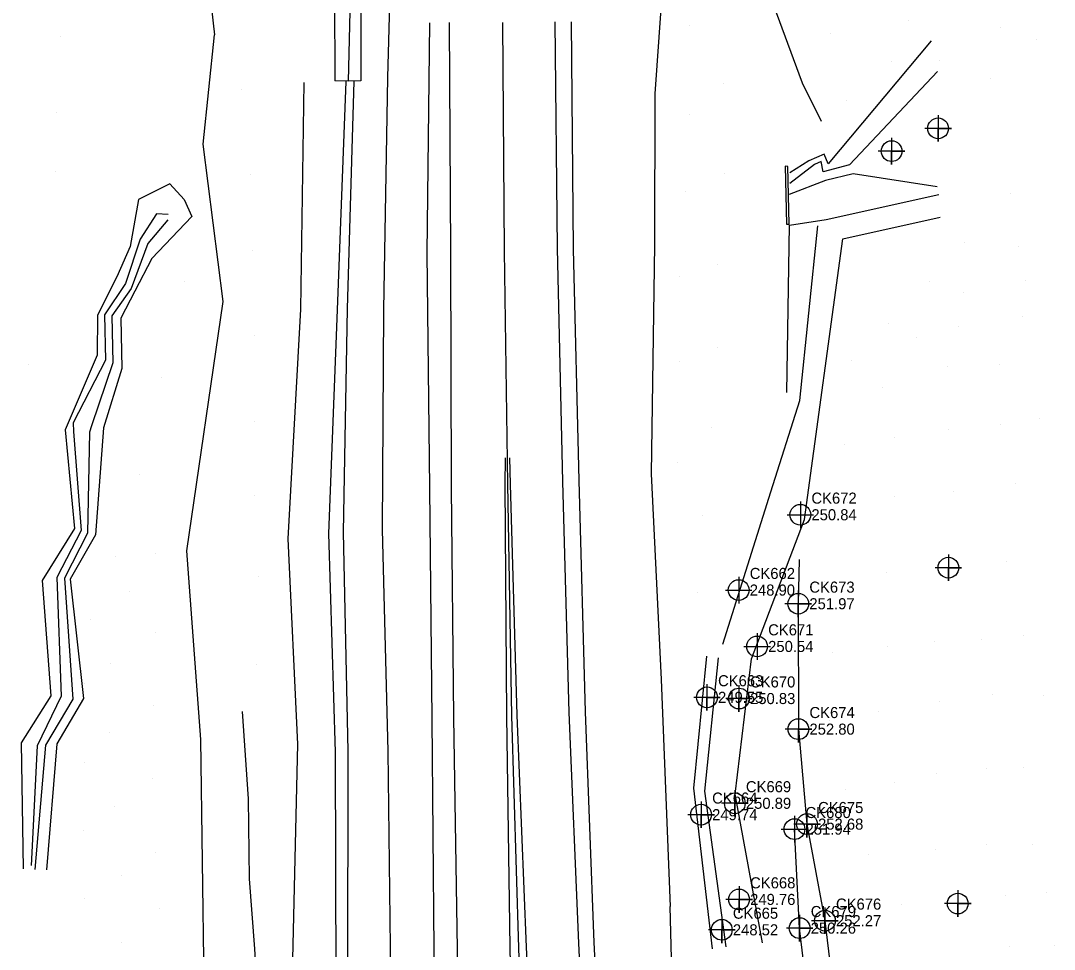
# Model space of a CAD drawing. Extents: x 1941547 to 1942851, y 663002 to 668358.
# Drawn here: x 1941855.2 to 1942088.7, y 667204.6 to 667414.3 of the extents above; entities that cross this region are included whole.
import ezdxf

# ---------------------------------------------------------------- set-up
doc = ezdxf.new("R2010")
doc.units = 0
for name, color, linetype in [('CTL NGS Vertical CELL', 7, 'Continuous'), ('Default Symbol CELL', 7, 'Continuous'), ('Exist DTM Breakline Cogo Elevation', 7, 'Continuous'), ('Exist DTM Breakline Cogo Number', 7, 'Continuous'), ('Exist DTM Breakline Cogo Point CELL', 7, 'Continuous'), ('Exist DTM Drainline Cogo Elevation', 7, 'Continuous'), ('Exist Property Iron Pin Cogo Number', 7, 'Continuous'), ('Exist Roads EOP Cogo Elevation', 7, 'Continuous'), ('Exist Roads EOP Cogo Number', 7, 'Continuous'), ('Exist Roads EOT', 7, 'Continuous'), ('Exist Utilities Telephone UG Cable SUE LOS C Cogo Elevation', 7, 'Continuous'), ('Exist Utilities Telephone UG FO SUE LOS C Cogo Elevation', 7, 'Continuous'), ('PH Exist DTM Breakline', 7, 'Continuous'), ('PH Exist DTM Point', 7, 'Continuous')]:
    doc.layers.add(name, color=color, linetype=linetype)

msp = doc.modelspace()

# ---------------------------------------------------------------- linework, layer by layer
at = {"layer": 'CTL NGS Vertical CELL'}
for points in [[(1942062.3, 667402.82), (1942042.4, 667381.75), (1942036.45, 667380.14), (1942035.97, 667382.48), (1942034.45, 667381.81), (1942028.95, 667377.47)], [(1941944.36, 666841.1), (1941940.55, 666899.2), (1941939.33, 666951.2), (1941935.62, 666998.45), (1941934.74, 667049.89), (1941931.25, 667098.44), (1941929.85, 667149.11), (1941926.42, 667197.25), (1941926.31, 667249.1), (1941924.77, 667298.53), (1941926.78, 667349), (1941928.74, 667400.53)], [(1941946.98, 666841.87), (1941943.17, 666899.66), (1941941.62, 666951.26), (1941938.82, 666998.62), (1941936.61, 667049.98), (1941933.24, 667098.55), (1941932.35, 667149.21), (1941929.12, 667196.95), (1941929.17, 667249.39), (1941928.09, 667298.81), (1941929.02, 667349.18), (1941930.48, 667400.62)], [(1942062.17, 667376.74), (1942043.22, 667379.65), (1942036.98, 667378.19), (1942028.76, 667375)], [(1941888.49, 667370.51), (1941885.84, 667370.67), (1941882.18, 667364.91), (1941878.86, 667354.96), (1941874.13, 667347.86), (1941874.39, 667337.64), (1941867.06, 667323.46), (1941867.16, 667321.53), (1941868.86, 667299.18), (1941863.38, 667288.53), (1941864.32, 667261.75), (1941858.91, 667250.6), (1941857.58, 667223.58)], [(1941888.41, 667369.27), (1941883.95, 667363.99), (1941880.16, 667353.83), (1941875.77, 667347.61), (1941876.03, 667337), (1941871.17, 667322.82), (1941870.74, 667321.4), (1941870.26, 667298.59), (1941865.12, 667288.42), (1941866.95, 667261.11), (1941860.83, 667250.71), (1941858.37, 667222.65)], [(1942011.46, 667204.71), (1942007.26, 667240.97), (1942010.15, 667270.83)], [(1942014.53, 667205.16), (1942009.75, 667240.36), (1942012.79, 667270.45)]]:
    msp.add_lwpolyline(points, dxfattribs=at)
at = {"layer": 'Exist DTM Breakline Cogo Number'}
for points in [[(1942031.29, 667305.73), (1942031.29, 667302.73)], [(1942028.29, 667302.73), (1942031.29, 667302.73)], [(1942031.29, 667302.73), (1942034.29, 667302.73)], [(1942031.29, 667302.73), (1942031.29, 667299.73)], [(1942017.36, 667288.73), (1942017.36, 667285.73)], [(1942014.36, 667285.73), (1942017.36, 667285.73)], [(1942017.36, 667285.73), (1942020.36, 667285.73)], [(1942017.36, 667285.73), (1942017.36, 667282.73)], [(1942021.52, 667276), (1942021.52, 667273)], [(1942018.52, 667273), (1942021.52, 667273)], [(1942021.52, 667273), (1942024.52, 667273)], [(1942021.52, 667273), (1942021.52, 667270)], [(1942029.96, 667234.76), (1942029.96, 667231.76)], [(1942026.96, 667231.76), (1942029.96, 667231.76)], [(1942029.96, 667231.76), (1942032.96, 667231.76)], [(1942029.96, 667231.76), (1942029.96, 667228.76)]]:
    msp.add_lwpolyline(points, dxfattribs=at)
for centre in [(1942031.29, 667302.73), (1942017.36, 667285.73), (1942021.52, 667273), (1942029.96, 667231.76)]:
    msp.add_circle(centre, 2.34, dxfattribs=at)
at = {"layer": 'Exist DTM Drainline Cogo Elevation'}
for points in [[(1942062.4, 667392.95), (1942062.4, 667386.95), (1942062.4, 667389.95), (1942065.4, 667389.95), (1942059.4, 667389.95)], [(1942051.9, 667387.81), (1942051.9, 667381.81), (1942051.9, 667384.81), (1942054.9, 667384.81), (1942048.9, 667384.81)], [(1942064.72, 667293.78), (1942064.72, 667287.78), (1942064.72, 667290.78), (1942067.72, 667290.78), (1942061.72, 667290.78)], [(1942066.84, 667217.95), (1942066.84, 667211.95), (1942066.84, 667214.95), (1942069.84, 667214.95), (1942063.84, 667214.95)]]:
    msp.add_lwpolyline(points, dxfattribs=at)
for centre in [(1942062.4, 667389.95), (1942051.9, 667384.81), (1942064.72, 667290.78), (1942066.84, 667214.95)]:
    msp.add_circle(centre, 2.34, dxfattribs=at)
at = {"layer": 'Exist Property Iron Pin Cogo Number'}
msp.add_lwpolyline([(1942008.85, 666690.79), (1942002.07, 666741.6), (1941996.47, 666793.56), (1941990.89, 666844.38), (1941986.33, 666894.98), (1941981.96, 666947.23), (1941978.03, 666998.38), (1941974.77, 667049.54), (1941971.64, 667101.97), (1941969.4, 667152.95), (1941967.69, 667204.95), (1941966.16, 667257.35), (1941965.22, 667309.63), (1941964.5, 667362.27), (1941964.07, 667413.88)], dxfattribs=at)
at = {"layer": 'Exist Roads EOP Cogo Number'}
for points in [[(1942030.82, 667285.64), (1942030.82, 667279.64), (1942030.82, 667282.64), (1942033.82, 667282.64), (1942027.82, 667282.64)], [(1942010.2, 667264.51), (1942010.2, 667258.51), (1942010.2, 667261.51), (1942013.2, 667261.51), (1942007.2, 667261.51)], [(1942017.43, 667264.24), (1942017.43, 667258.24), (1942017.43, 667261.24), (1942020.43, 667261.24), (1942014.43, 667261.24)], [(1942030.85, 667257.33), (1942030.85, 667251.33), (1942030.85, 667254.33), (1942033.85, 667254.33), (1942027.85, 667254.33)], [(1942016.49, 667240.59), (1942016.49, 667234.59), (1942016.49, 667237.59), (1942019.49, 667237.59), (1942013.49, 667237.59)], [(1942008.87, 667238.02), (1942008.87, 667232.02), (1942008.87, 667235.02), (1942011.87, 667235.02), (1942005.87, 667235.02)], [(1942032.79, 667235.89), (1942032.79, 667229.89), (1942032.79, 667232.89), (1942035.79, 667232.89), (1942029.79, 667232.89)], [(1942017.45, 667218.89), (1942017.45, 667212.89), (1942017.45, 667215.89), (1942020.45, 667215.89), (1942014.45, 667215.89)], [(1942036.84, 667214.09), (1942036.84, 667208.09), (1942036.84, 667211.09), (1942039.84, 667211.09), (1942033.84, 667211.09)], [(1942013.55, 667212.03), (1942013.55, 667206.03), (1942013.55, 667209.03), (1942016.55, 667209.03), (1942010.55, 667209.03)], [(1942031.13, 667212.41), (1942031.13, 667206.41), (1942031.13, 667209.41), (1942034.13, 667209.41), (1942028.13, 667209.41)]]:
    msp.add_lwpolyline(points, dxfattribs=at)
for centre in [(1942030.82, 667282.64), (1942010.2, 667261.51), (1942017.43, 667261.24), (1942030.85, 667254.33), (1942016.49, 667237.59), (1942008.87, 667235.02), (1942032.79, 667232.89), (1942017.45, 667215.89), (1942036.84, 667211.09), (1942013.55, 667209.03), (1942031.13, 667209.41)]:
    msp.add_circle(centre, 2.34, dxfattribs=at)
at = {"layer": 'Exist Roads EOT'}
for points in [[(1941951.98, 667413.81), (1941952.26, 667362.04), (1941952.46, 667308.89), (1941952.97, 667256.94), (1941953.75, 667204.68), (1941954.75, 667152.02), (1941956.26, 667100.95), (1941958.71, 667048.32), (1941960.84, 666996.9), (1941962.55, 666945.54), (1941964.6, 666892.87), (1941965.91, 666841.69), (1941967.14, 666790.13), (1941967.35, 666775.96), (1941965.99, 666756.26), (1941960.31, 666738.22), (1941950.2, 666725.25), (1941933.38, 666712.58), (1941911.61, 666702.83), (1941884.69, 666696.42), (1941884.07, 666696.32)], [(1942026.6, 666693.52), (1942019.88, 666743.94), (1942013.54, 666795.86), (1942007.82, 666846.76), (1942002.76, 666897.1), (1941997.85, 666949.23), (1941993.62, 666999.88), (1941989.95, 667051.06), (1941986.57, 667103.22), (1941983.76, 667154.19), (1941981.25, 667205.98), (1941979.11, 667258.1), (1941977.64, 667310.25), (1941976.44, 667362.8), (1941975.95, 667413.99)], [(1942003.35, 666690.27), (1941996.18, 666740.71), (1941990.55, 666792.95), (1941985.7, 666843.93), (1941981.39, 666894.52), (1941977.35, 666947.08), (1941973.82, 666998.13), (1941970.64, 667049.39), (1941968.27, 667101.82), (1941966.8, 667152.88), (1941965.74, 667205.04), (1941965, 667257.27), (1941964.59, 667309.55), (1941964.7, 667315.61)], [(1942014.4, 666691.83), (1942008.07, 666742.35), (1942001.91, 666794.2), (1941996.25, 666845.1), (1941991.05, 666895.6), (1941986.23, 666947.8), (1941981.87, 666998.75), (1941978.14, 667049.88), (1941974.78, 667102.32), (1941971.91, 667153.2), (1941969.44, 667205.09), (1941967.31, 667257.47), (1941965.84, 667309.66), (1941965.66, 667315.58)]]:
    msp.add_lwpolyline(points, dxfattribs=at)
at = {"layer": 'Exist Utilities Telephone UG Cable SUE LOS C Cogo Elevation'}
for points in [[(1941947.53, 667413.75), (1941946.96, 667361.74), (1941947.54, 667308.73), (1941948.08, 667256.56), (1941948.52, 667204.49), (1941949.24, 667151.67), (1941952.06, 667100.74), (1941955.32, 667048.01), (1941957.95, 666996.74), (1941959.85, 666945.25), (1941962.44, 666892.69), (1941963.58, 666841.54), (1941964.58, 666789.92), (1941964.71, 666776.07), (1941964.25, 666756.23), (1941958.52, 666739.42), (1941948.3, 666727.6), (1941930.93, 666716.38), (1941910.35, 666706.81), (1941883.98, 666699.72), (1941884.18, 666697.45), (1941835.96, 666689.1), (1941789.23, 666683.83)], [(1942029.9, 666693.84), (1942023.63, 666744.48), (1942017.17, 666796.27), (1942011.56, 666847.08), (1942006.59, 666897.47), (1942002, 666949.63), (1941997.54, 667000.16), (1941993.96, 667051.35), (1941990.36, 667103.49), (1941987.34, 667154.41), (1941984.74, 667206.16), (1941982.79, 667258.26), (1941981.31, 667310.45), (1941980.08, 667362.7), (1941979.57, 667414.02)], [(1942029.9, 666693.84), (1942023.63, 666744.48), (1942017.17, 666796.27), (1942011.56, 666847.08), (1942006.59, 666897.47), (1942002, 666949.63), (1941997.54, 667000.16), (1941993.96, 667051.35), (1941990.36, 667103.49), (1941987.34, 667154.41), (1941984.74, 667206.16), (1941982.79, 667258.26), (1941981.31, 667310.45), (1941980.08, 667362.7), (1941979.57, 667414.02)]]:
    msp.add_lwpolyline(points, dxfattribs=at)
at = {"layer": 'Exist Utilities Telephone UG FO SUE LOS C Cogo Elevation'}
for p, q in [((1941896.45, 667386.37), (1941898.94, 667411.09)), ((1941892.09, 667373.92), (1941888.92, 667377.45)), ((1941895.86, 667252), (1941892.74, 667294.6))]:
    msp.add_line(p, q, dxfattribs=at)
for points in [[(1941879.59, 667597.4), (1941880.92, 667567.08), (1941886.17, 667524.12), (1941892.76, 667465.98), (1941898.94, 667411.09)], [(1942058.97, 667471.88), (1942056.59, 667466.81), (1942043.21, 667443.37), (1942043.12, 667431.55), (1942034.51, 667434.31), (1942029.48, 667455.03), (1942025.79, 667468.06), (1942018.93, 667476.04), (1942008.95, 667476.26), (1941996.74, 667467.91), (1942001.16, 667436.21), (1941998.43, 667397.75), (1941998.37, 667363.65), (1941997.58, 667311.94), (1941999.85, 667265.5), (1942001.89, 667214.29)], [(1941953.68, 666843.33), (1941951.66, 666900.41), (1941949.77, 666951.26), (1941948.98, 666999.44), (1941946.86, 667050.67), (1941943.18, 667099.35), (1941941.85, 667149.88), (1941938.77, 667198.77), (1941938.16, 667249.33), (1941936.9, 667299.38), (1941937.19, 667349.01), (1941938.12, 667401.41), (1941938.73, 667423.66)], [(1942060.84, 667409.73), (1942037.57, 667381.92), (1942036.69, 667384.16), (1942033.22, 667382.61), (1942028.88, 667379.88)], [(1941940.44, 666840.55), (1941933.09, 666898.2), (1941933.3, 666950.95), (1941928.6, 666997.79), (1941925.81, 667049.37), (1941920.3, 667096.89), (1941919.5, 667148.93), (1941916.49, 667195.96), (1941917.83, 667250.95), (1941915.62, 667297.28), (1941918.48, 667349.12), (1941919.21, 667400.3)], [(1941892.74, 667294.6), (1941900.93, 667350.86), (1941896.45, 667386.37)], [(1942028.46, 667381.34), (1942027.89, 667381.4), (1942028.17, 667368.32), (1942028.73, 667368.31), (1942028.46, 667381.34)], [(1941888.92, 667377.45), (1941881.83, 667373.88), (1941879.94, 667363.26), (1941876.91, 667356.46), (1941872.54, 667347.76), (1941872.45, 667338.75), (1941865.25, 667321.87), (1941867.38, 667299.59), (1941860.05, 667287.86), (1941862, 667261.86), (1941855.33, 667251.26), (1941855.76, 667222.79)], [(1941892.09, 667373.92), (1941893.87, 667370.07), (1941884.79, 667360.54), (1941881, 667353.21), (1941877.79, 667347.11), (1941878.06, 667335.73), (1941873.91, 667322.32), (1941872.09, 667298.18), (1941866.39, 667288.15), (1941869.36, 667261.27), (1941863.35, 667251.03), (1941861.02, 667222.59)], [(1942028.22, 667330.29), (1942028.82, 667368.07), (1942037.14, 667369.41), (1942062.59, 667375.05)], [(1942022.74, 667206.08), (1942016.6, 667239.65), (1942020.25, 667270.18), (1942032.24, 667301.64), (1942040.9, 667364.99), (1942062.88, 667369.94)], [(1942013.76, 667273.5), (1942024.65, 667307.87), (1942031.14, 667328.49), (1942035.21, 667367.95)], [(1942031.05, 667292.59), (1942030.82, 667282.64), (1942030.85, 667254.33), (1942032.79, 667232.89), (1942036.84, 667211.09), (1942039.91, 667185.52), (1942033.83, 667187.08), (1942031.13, 667209.41), (1942029.96, 667231.76)], [(1941905.59, 666991.1), (1941902.17, 667040.73), (1941900.73, 667092.27), (1941897.78, 667143.97), (1941896.66, 667196.91), (1941895.86, 667252)], [(1942032.72, 666744.96), (1942027.14, 666797.25), (1942020.56, 666847.68), (1942015.28, 666898.21), (1942009.12, 666950.56), (1942006.12, 667001.04), (1942002.66, 667052.7), (1942001.92, 667104.94), (1942003.5, 667152.75), (1942001.89, 667214.29)]]:
    msp.add_lwpolyline(points, dxfattribs=at)
at = {"layer": 'PH Exist DTM Breakline'}
for p, q in [((1941926.08, 667422.36), (1941926.12, 667400.66)), ((1941929.21, 667400.64), (1941929.73, 667421.71)), ((1941932.03, 667422.37), (1941932.06, 667400.67))]:
    msp.add_line(p, q, dxfattribs=at)
for points in [[(1942036.07, 667391.49), (1942031.78, 667400.13), (1942024.62, 667419.53)], [(1941932.06, 667400.67), (1941929.21, 667400.64), (1941926.12, 667400.66)], [(1941913.22, 667113.13), (1941911.57, 667132.08), (1941909.81, 667150.09), (1941909.63, 667169.85), (1941909.15, 667187.66), (1941908.05, 667204.76), (1941906.91, 667220.55), (1941906.63, 667238.6), (1941905.3, 667258.31)]]:
    msp.add_lwpolyline(points, dxfattribs=at)
at = {"layer": 'PH Exist DTM Point'}
for p, q in [((1942055.71, 667414.22), (1942055.71, 667414.22)), ((1942006.36, 667413.26), (1942006.36, 667413.26)), ((1942038.09, 667411.42), (1942038.09, 667411.42)), ((1942076.54, 667412.75), (1942076.54, 667412.75)), ((1941864.24, 667410.66), (1941864.24, 667410.66)), ((1942084.6, 667409.95), (1942084.6, 667409.95)), ((1942051.81, 667405.05), (1942051.81, 667405.05)), ((1942062.75, 667405.27), (1942062.75, 667405.27)), ((1942014.01, 667399.99), (1942014.01, 667399.99)), ((1942074.23, 667401.1), (1942074.23, 667401.1)), ((1941905.17, 667398.64), (1941905.17, 667398.64)), ((1942041.6, 667396.22), (1942041.6, 667396.22)), ((1941863.24, 667393.5), (1941863.24, 667393.5)), ((1942006.32, 667392.98), (1942006.32, 667392.98)), ((1941862.98, 667380.17), (1941862.98, 667380.17)), ((1941907.11, 667379.55), (1941907.11, 667379.55)), ((1942014.27, 667379.74), (1942014.27, 667379.74)), ((1942005.25, 667375.73), (1942005.25, 667375.73)), ((1942078.74, 667375.32), (1942078.74, 667375.32)), ((1941907.51, 667362.42), (1941907.51, 667362.42)), ((1942068.32, 667364.1), (1942068.32, 667364.1)), ((1942080.61, 667363.17), (1942080.61, 667363.17)), ((1942012.47, 667359.33), (1942012.47, 667359.33)), ((1941892.17, 667355.28), (1941892.17, 667355.28)), ((1942004.1, 667356.48), (1942004.1, 667356.48)), ((1942060.45, 667355.43), (1942060.45, 667355.43)), ((1942082.21, 667355.66), (1942082.21, 667355.66)), ((1942068.12, 667352.97), (1942068.12, 667352.97)), ((1942051.31, 667345.93), (1942051.31, 667345.93)), ((1942081.57, 667347.46), (1942081.57, 667347.46)), ((1942066.91, 667345.33), (1942066.91, 667345.33)), ((1941907.92, 667343.15), (1941907.92, 667343.15)), ((1942057.62, 667342.78), (1942057.62, 667342.78)), ((1942012.63, 667340.39), (1942012.63, 667340.39)), ((1941857.03, 667336.58), (1941857.03, 667336.58)), ((1942004.06, 667337.24), (1942004.06, 667337.24)), ((1942042.84, 667337.45), (1942042.84, 667337.45)), ((1942076.3, 667336.7), (1942076.3, 667336.7)), ((1942064.63, 667336.19), (1942064.63, 667336.19)), ((1941886.91, 667333.73), (1941886.91, 667333.73)), ((1942049.95, 667331.46), (1942049.95, 667331.46)), ((1941907.96, 667323.84), (1941907.96, 667323.84)), ((1942011.23, 667322.53), (1942011.23, 667322.53)), ((1942076.52, 667323.21), (1942076.52, 667323.21)), ((1942085.4, 667324.41), (1942085.4, 667324.41)), ((1942052.63, 667320.16), (1942052.63, 667320.16)), ((1942064.78, 667321.88), (1942064.78, 667321.88)), ((1942041.27, 667318.64), (1942041.27, 667318.64)), ((1942003.62, 667314.56), (1942003.62, 667314.56)), ((1941882.11, 667311.92), (1941882.11, 667311.92)), ((1942079.83, 667309.69), (1942079.83, 667309.69)), ((1941908.1, 667307.13), (1941908.1, 667307.13)), ((1942052.52, 667306.83), (1942052.52, 667306.83)), ((1942065.82, 667308.05), (1942065.82, 667308.05)), ((1942041.95, 667305.59), (1942041.95, 667305.59)), ((1942009.25, 667302.62), (1942009.25, 667302.62)), ((1941876.55, 667293.3), (1941876.55, 667293.3)), ((1941885.74, 667294.07), (1941885.74, 667294.07)), ((1942077.79, 667292.14), (1942077.79, 667292.14)), ((1942064.18, 667290.9), (1942064.18, 667290.9)), ((1941908.81, 667288.84), (1941908.81, 667288.84)), ((1942036.78, 667287.73), (1942036.78, 667287.73)), ((1942050.72, 667289.59), (1942050.72, 667289.59)), ((1941879.85, 667285.41), (1941879.85, 667285.41)), ((1942008.12, 667285.08), (1942008.12, 667285.08)), ((1941870.97, 667278.98), (1941870.97, 667278.98)), ((1941885.75, 667276.16), (1941885.75, 667276.16)), ((1942061.58, 667274.18), (1942061.58, 667274.18)), ((1942072.29, 667274.54), (1942072.29, 667274.54)), ((1942081.7, 667275.54), (1942081.7, 667275.54)), ((1942038.65, 667271.72), (1942038.65, 667271.72)), ((1942050.92, 667273.09), (1942050.92, 667273.09)), ((1941875.45, 667269.1), (1941875.45, 667269.1)), ((1941908.45, 667268.92), (1941908.45, 667268.92)), ((1941869.59, 667264.74), (1941869.59, 667264.74)), ((1942074.58, 667262.15), (1942074.58, 667262.15)), ((1942086.23, 667261.91), (1942086.23, 667261.91)), ((1941885.29, 667259.63), (1941885.29, 667259.63)), ((1942062.7, 667260.59), (1942062.7, 667260.59)), ((1942048.95, 667258.23), (1942048.95, 667258.23)), ((1942037.76, 667256.21), (1942037.76, 667256.21)), ((1941875.32, 667253.49), (1941875.32, 667253.49)), ((1941869.54, 667246.69), (1941869.54, 667246.69)), ((1942073.32, 667245.46), (1942073.32, 667245.46)), ((1942081.75, 667245.65), (1942081.75, 667245.65)), ((1941884.97, 667243.19), (1941884.97, 667243.19)), ((1942062.14, 667244.4), (1942062.14, 667244.4)), ((1942041.43, 667240.78), (1942041.43, 667240.78)), ((1942052.5, 667242.35), (1942052.5, 667242.35)), ((1941876.35, 667236.77), (1941876.35, 667236.77)), ((1941869.36, 667231.36), (1941869.36, 667231.36)), ((1942061.92, 667227.1), (1942061.92, 667227.1)), ((1942073.4, 667228.18), (1942073.4, 667228.18)), ((1942083.69, 667228.29), (1942083.69, 667228.29)), ((1941885.7, 667226.52), (1941885.7, 667226.52)), ((1942046.67, 667226.03), (1942046.67, 667226.03)), ((1941878.02, 667221.36), (1941878.02, 667221.36)), ((1942086.96, 667217.51), (1942086.96, 667217.51)), ((1941869.54, 667216.14), (1941869.54, 667216.14)), ((1942064.82, 667215.7), (1942064.82, 667215.7)), ((1942077.55, 667216.73), (1942077.55, 667216.73)), ((1941886.57, 667213.87), (1941886.57, 667213.87)), ((1942043.79, 667213.97), (1942043.79, 667213.97)), ((1942054.09, 667214.75), (1942054.09, 667214.75)), ((1941878.04, 667206.27), (1941878.04, 667206.27)), ((1942078.44, 667205.37), (1942078.44, 667205.37)), ((1942088.65, 667205.55), (1942088.65, 667205.55))]:
    msp.add_line(p, q, dxfattribs=at)

# ---------------------------------------------------------------- texts
at = {"layer": 'Default Symbol CELL'}
for s, p in [('250.84', (1942033.79, 667301.48)), ('248.90', (1942019.86, 667284.48)), ('250.54', (1942024.02, 667271.75)), ('251.94', (1942032.46, 667230.51))]:
    msp.add_text(s, height=2.5, dxfattribs=at).set_placement(p)
at = {"layer": 'Exist DTM Breakline Cogo Elevation'}
for s, p in [('CK672', (1942033.79, 667305.23)), ('CK662', (1942019.86, 667288.23)), ('CK671', (1942024.02, 667275.5)), ('CK680', (1942032.46, 667234.26))]:
    msp.add_text(s, height=2.5, dxfattribs=at).set_placement(p)
at = {"layer": 'Exist DTM Breakline Cogo Point CELL'}
for s, p in [('251.97', (1942033.32, 667281.39)), ('249.55', (1942012.7, 667260.26)), ('250.83', (1942019.93, 667259.99)), ('252.80', (1942033.35, 667253.08)), ('250.89', (1942018.99, 667236.34)), ('249.74', (1942011.37, 667233.77)), ('252.68', (1942035.29, 667231.64)), ('249.76', (1942019.95, 667214.64)), ('250.26', (1942033.63, 667208.16)), ('252.27', (1942039.34, 667209.84)), ('248.52', (1942016.05, 667207.78))]:
    msp.add_text(s, height=2.5, dxfattribs=at).set_placement(p)
at = {"layer": 'Exist Roads EOP Cogo Elevation'}
for s, p in [('CK673', (1942033.32, 667285.14)), ('CK663', (1942012.7, 667264.01)), ('CK670', (1942019.93, 667263.74)), ('CK674', (1942033.35, 667256.83)), ('CK669', (1942018.99, 667240.09)), ('CK664', (1942011.37, 667237.52)), ('CK675', (1942035.29, 667235.39)), ('CK668', (1942019.95, 667218.39)), ('CK676', (1942039.34, 667213.59)), ('CK665', (1942016.05, 667211.53)), ('CK679', (1942033.63, 667211.91))]:
    msp.add_text(s, height=2.5, dxfattribs=at).set_placement(p)

doc.saveas('drawing.dxf')
